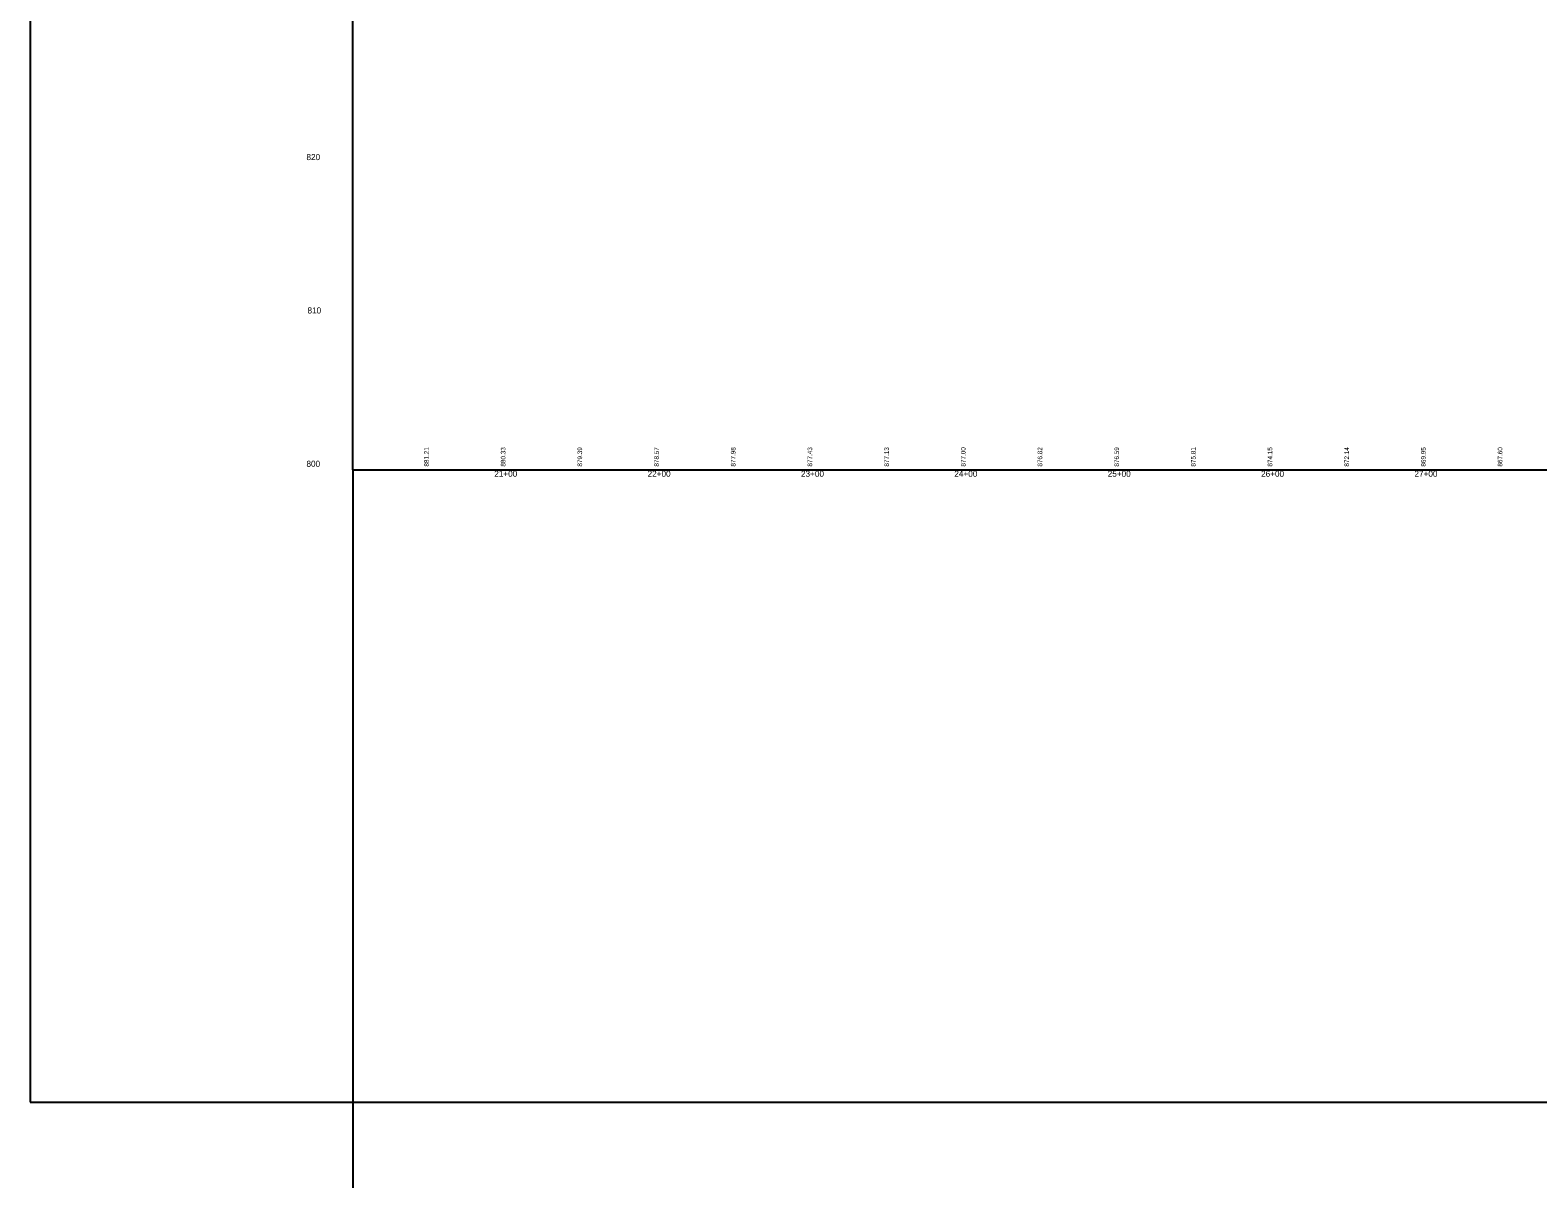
# Model space of a CAD drawing. Extents: x 1733669 to 1739080, y 1214897 to 1219897.
# Drawn here: x 1733669 to 1734652, y 1216935 to 1217684 of the extents above; entities that cross this region are included whole.
import ezdxf

# ---------------------------------------------------------------- set-up
doc = ezdxf.new("R2010")
doc.units = 0
for name, color, linetype in [('Default', 7, 'Continuous'), ('RD_DDB_ElevTX', 7, 'Continuous'), ('RD_DDB_StaTX', 7, 'Continuous'), ('RD_DDB_StripGrade', 7, 'Continuous'), ('RD_Sketch8', 7, 'Continuous')]:
    doc.layers.add(name, color=color, linetype=linetype)

msp = doc.modelspace()

# ---------------------------------------------------------------- linework, layer by layer
at = {"layer": 'Default'}
for q in [(1733879.77, 1219896.77), (1739079.77, 1217396.77), (1733879.77, 1214896.77)]:
    msp.add_line((1733879.77, 1217396.77), q, dxfattribs=at)
at = {"layer": 'RD_Sketch8'}
msp.add_lwpolyline([(1733669.38, 1216984.56), (1737269.38, 1216984.56), (1737269.38, 1219184.56), (1733669.38, 1219184.56)], close=True, dxfattribs=at)

# ---------------------------------------------------------------- texts
at = {"layer": 'Default'}
for s, p in [('S56', (1733879.77, 1217396.83)), ('S56', (1733879.77, 1217396.82)), ('2000.000000', (1733879.77, 1217396.81)), ('800', (1733879.77, 1217396.8)), ('100', (1733879.77, 1217396.79)), ('10', (1733879.77, 1217396.78)), ('NOGAP', (1733879.77, 1217396.78))]:
    msp.add_text(s, height=0.00975, dxfattribs=at).set_placement(p)
at = {"layer": 'RD_DDB_ElevTX'}
for s, p in [('820', (1733849.53, 1217598.77)), ('810', (1733850.2, 1217498.77)), ('800', (1733849.53, 1217398.77))]:
    msp.add_text(s, height=4, dxfattribs=at).set_placement(p)
at = {"layer": 'RD_DDB_StaTX'}
for s, p in [('21+00', (1733971.95, 1217392.27)), ('21+00', (1733971.95, 1217392.27)), ('21+00', (1733971.95, 1217392.27)), ('22+00', (1734071.95, 1217392.27)), ('22+00', (1734071.95, 1217392.27)), ('22+00', (1734071.95, 1217392.27)), ('23+00', (1734171.95, 1217392.27)), ('23+00', (1734171.95, 1217392.27)), ('23+00', (1734171.95, 1217392.27)), ('24+00', (1734271.95, 1217392.27)), ('24+00', (1734271.95, 1217392.27)), ('24+00', (1734271.95, 1217392.27)), ('25+00', (1734371.95, 1217392.27)), ('25+00', (1734371.95, 1217392.27)), ('25+00', (1734371.95, 1217392.27)), ('26+00', (1734471.95, 1217392.27)), ('26+00', (1734471.95, 1217392.27)), ('26+00', (1734471.95, 1217392.27)), ('27+00', (1734571.95, 1217392.27)), ('27+00', (1734571.95, 1217392.27)), ('27+00', (1734571.95, 1217392.27))]:
    msp.add_text(s, height=4, dxfattribs=at).set_placement(p)
at = {"layer": 'RD_DDB_StripGrade'}
for s, p in [('881.21', (1733929.27, 1217398.93)), ('880.33', (1733979.27, 1217398.93)), ('879.39', (1734029.27, 1217398.93)), ('878.57', (1734079.27, 1217398.93)), ('877.98', (1734129.27, 1217398.93)), ('877.43', (1734179.27, 1217398.93)), ('877.13', (1734229.27, 1217398.93)), ('877.00', (1734279.27, 1217398.93)), ('876.82', (1734329.27, 1217398.93)), ('876.59', (1734379.27, 1217398.93)), ('875.81', (1734429.27, 1217398.93)), ('874.15', (1734479.27, 1217398.93)), ('872.14', (1734529.27, 1217398.93)), ('869.95', (1734579.27, 1217398.93)), ('867.60', (1734629.27, 1217398.93))]:
    msp.add_text(s, height=3, rotation=90, dxfattribs=at).set_placement(p)

doc.saveas('drawing.dxf')
